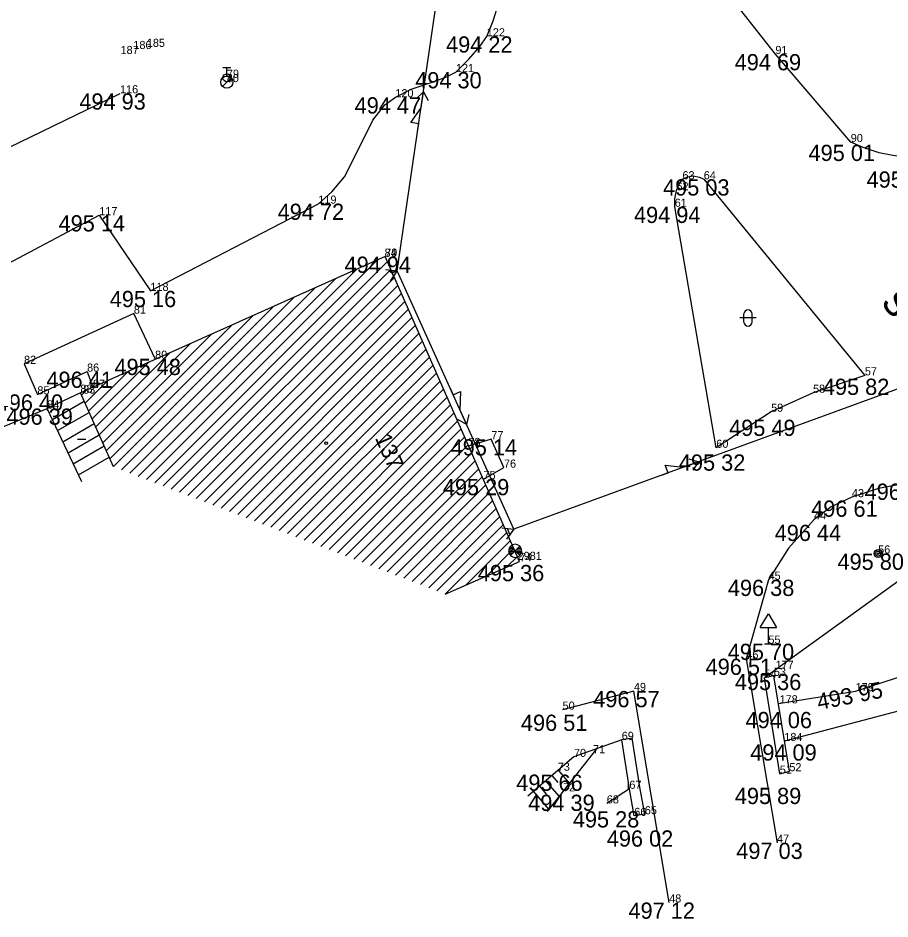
# Model space of a CAD drawing. Extents: x -559180 to -551373, y -1076947 to -1072071.
# Drawn here: x -553489.1 to -553435.4, y -1076713.8 to -1076658.3 of the extents above; entities that cross this region are included whole.
import ezdxf

# ---------------------------------------------------------------- set-up
doc = ezdxf.new("R2010")
doc.units = 0
for name, color, linetype in [('12_PLOTY', 7, 'Continuous'), ('14_BUDOVY', 7, 'Continuous'), ('17_KOMUNIKACE', 7, 'Continuous'), ('18_POLOHOPIS', 7, 'Continuous'), ('1_VODA_ZN', 7, 'Continuous'), ('20_EL_ZN', 7, 'Continuous'), ('23_HRANY', 7, 'Continuous'), ('26_SRAFY', 7, 'Continuous'), ('27_HRANA_PATA', 7, 'Continuous'), ('28_VODA', 7, 'Continuous'), ('32', 7, 'Continuous'), ('33', 7, 'Continuous'), ('3_BODY', 7, 'Continuous'), ('45_ZN_KULTURY', 7, 'Continuous'), ('47_ZN_STAV_OBJ$', 7, 'Continuous'), ('48_DOPRAVA_ZN', 7, 'Continuous'), ('52_POPIS_UCELOVY', 7, 'Continuous'), ('54_C_POPISNA', 7, 'Continuous'), ('6_VYSKY', 7, 'Continuous'), ('NNnadzemní', 7, 'Continuous')]:
    doc.layers.add(name, color=color, linetype=linetype)

# ---------------------------------------------------------------- blocks, each defined once
blk = doc.blocks.new('POINT_DISPLAY')
blk.add_line((0, 0), (0, 0))
blk = doc.blocks.new('DZ')
at = {"layer": '48_DOPRAVA_ZN'}
for p, q in [((-0.5, 1), (0, 1.85)), ((0, 1.85), (0.5, 1)), ((-0.5, 1), (0.5, 1)), ((0, 0), (0, 1)), ((-0.25, 0), (0.25, 0))]:
    blk.add_line(p, q, dxfattribs=at)
blk = doc.blocks.new('SLB')
at = {"layer": '20_EL_ZN'}
for radius in [0.25, 0.158, 0.05]:
    blk.add_circle((0, 0), radius, dxfattribs=at)
blk = doc.blocks.new('BZ')
at = {"layer": '47_ZN_STAV_OBJ$'}
blk.add_circle((0, 0), 0.0875, dxfattribs=at)
blk = doc.blocks.new('BD')
at = {"layer": '47_ZN_STAV_OBJ$'}
blk.add_line((-0.25, 0), (0.25, 0), dxfattribs=at)
blk = doc.blocks.new('NEPLOD')
at = {"layer": '45_ZN_KULTURY'}
for p, q in [((0.519, 0.01), (-0.481, 0.01)), ((-0.231, -0.24), (-0.231, 0.26)), ((0.269, -0.24), (0.269, 0.26))]:
    blk.add_line(p, q, dxfattribs=at)
for centre, start, end in [((0.019, 0.26), 0, 180), ((0.019, -0.24), 180, 0)]:
    blk.add_arc(centre, 0.25, start, end, dxfattribs=at)
blk = doc.blocks.new('SV')
at = {"layer": '1_VODA_ZN'}
blk.add_circle((0, 0), 0.25, dxfattribs=at)
blk = doc.blocks.new('HYP')
at = {"layer": '1_VODA_ZN'}
for p, q in [((-0.25, 0.9), (0.25, 0.9)), ((0, 0.375), (0, 0.9)), ((-0.265, -0.265), (0.265, 0.265))]:
    blk.add_line(p, q, dxfattribs=at)
blk.add_circle((0, 0), 0.375, dxfattribs=at)
blk = doc.blocks.new('NZ')
at = {"layer": '33'}
for p, q in [((-0.074, 0.04), (-0.401, 0.04)), ((-0.158, 0.151), (-0.349, 0.151)), ((0.376, 0.036), (0.055, 0.035)), ((0.348, 0.134), (0.145, 0.135)), ((-0.074, -0.054), (-0.372, -0.055)), ((-0.175, -0.16), (-0.361, -0.16)), ((0.37, -0.065), (0.089, -0.064)), ((0.342, -0.155), (0.162, -0.155))]:
    blk.add_line(p, q, dxfattribs=at)
for points in [[(0, 0), (-0.285, 0.285)], [(-0.285, -0.285), (0, 0)], [(0.285, 0.285), (0, 0)], [(0, 0), (0.285, -0.285)]]:
    blk.add_lwpolyline(points, dxfattribs=at)
for start, end in [(135.0044, 225.0044), (45, 135), (315.0044, 45.0044), (225, 315)]:
    blk.add_arc((0, 0), 0.403, start, end, dxfattribs=at)
blk = doc.blocks.new('KONZ')
at = {"layer": '20_EL_ZN'}
for p, q in [((-0.351, 0), (0, 0.65)), ((0, 0.65), (0.4, 0)), ((0.215, 0.3), (-0.188, 0.3))]:
    blk.add_line(p, q, dxfattribs=at)
blk = doc.blocks.new('ELNN')
at = {"layer": '20_EL_ZN'}
for p, q in [((0, 0), (0.5, 0)), ((0.5, 0), (0.5, 0.5)), ((0.5, 0.5), (1.5, 0)), ((1.5, 0), (2.5, 0))]:
    blk.add_line(p, q, dxfattribs=at)
blk.add_lwpolyline([(2, 0.375), (2.5, 0), (2, -0.375)], dxfattribs=at)

msp = doc.modelspace()

# ---------------------------------------------------------------- linework, layer by layer
at = {"layer": '12_PLOTY'}
msp.add_line((-553490.15, -1076683.51), (-553487.27, -1076682.33), dxfattribs=at)
at = {"layer": '14_BUDOVY'}
for p, q in [((-553466.45, -1076672.98), (-553485.22, -1076681.36)), ((-553458.18, -1076691.74), (-553466.45, -1076672.98)), ((-553485.22, -1076681.36), (-553487.27, -1076682.33)), ((-553483.182, -1076685.926), (-553485.22, -1076681.36)), ((-553485.131, -1076686.85), (-553487.27, -1076682.33)), ((-553462.755, -1076693.757), (-553458.18, -1076691.74))]:
    msp.add_line(p, q, dxfattribs=at)
at = {"layer": '17_KOMUNIKACE'}
for p, q in [((-553442.43, -1076660.51), (-553449.75, -1076651.19)), ((-553437.79, -1076665.93), (-553442.43, -1076660.51)), ((-553490.98, -1076666.9), (-553482.78, -1076662.93)), ((-553446.84, -1076668.22), (-553436.92, -1076680.29)), ((-553480.91, -1076675.09), (-553470.57, -1076669.72)), ((-553446.07, -1076684.75), (-553448.63, -1076669.91)), ((-553497.8, -1076677.69), (-553484.06, -1076670.43)), ((-553484.06, -1076670.43), (-553480.91, -1076675.09)), ((-553436.92, -1076680.29), (-553440.11, -1076681.36)), ((-553440.11, -1076681.36), (-553442.69, -1076682.53)), ((-553442.69, -1076682.53), (-553446.07, -1076684.75)), ((-553442.85, -1076692.87), (-553444.22, -1076697.73)), ((-553444.22, -1076697.73), (-553442.33, -1076709.06)), ((-553451.14, -1076699.72), (-553455.53, -1076700.87)), ((-553448.97, -1076712.74), (-553451.14, -1076699.72))]:
    msp.add_line(p, q, dxfattribs=at)
for points in [[(-553460.2, -1076659.42), (-553459.798, -1076658.474), (-553459.578, -1076657.747), (-553459.45, -1076656.63)], [(-553462.1, -1076661.62), (-553461.3, -1076660.823), (-553460.624, -1076660.045), (-553460.2, -1076659.42)], [(-553465.83, -1076663.17), (-553464.865, -1076662.681), (-553463.632, -1076662.259), (-553462.719, -1076661.938), (-553462.1, -1076661.62)], [(-553470.57, -1076669.72), (-553469.74, -1076668.986), (-553468.955, -1076668.073), (-553467.713, -1076665.59), (-553467.206, -1076664.576), (-553466.471, -1076663.638), (-553465.83, -1076663.17)], [(-553434.38, -1076666.87), (-553435.205, -1076666.747), (-553436.046, -1076666.591), (-553437.033, -1076666.272), (-553437.79, -1076665.93)], [(-553448.15, -1076668.22), (-553447.837, -1076668.059), (-553447.488, -1076668.014), (-553447.105, -1076668.081), (-553446.84, -1076668.22)], [(-553448.52, -1076668.9), (-553448.355, -1076668.52), (-553448.15, -1076668.22)], [(-553448.63, -1076669.91), (-553448.625, -1076669.421), (-553448.52, -1076668.9)], [(-553434.43, -1076686.95), (-553436.09, -1076687.26), (-553437.72, -1076687.79)], [(-553437.72, -1076687.79), (-553438.993, -1076688.374), (-553440.05, -1076689.16)], [(-553440.05, -1076689.16), (-553441.619, -1076690.919), (-553442.85, -1076692.87)]]:
    msp.add_lwpolyline(points, dxfattribs=at)
at = {"layer": '18_POLOHOPIS'}
for p, q in [((-553481.93, -1076676.49), (-553488.69, -1076679.58)), ((-553480.62, -1076679.27), (-553481.93, -1076676.49)), ((-553488.69, -1076679.58), (-553487.87, -1076681.46)), ((-553487.87, -1076681.46), (-553484.81, -1076680.06)), ((-553484.81, -1076680.06), (-553484.45, -1076681.06)), ((-553459.92, -1076684.22), (-553461.33, -1076684.64)), ((-553459.14, -1076685.97), (-553459.92, -1076684.22)), ((-553460.4, -1076686.67), (-553459.14, -1076685.97)), ((-553442.52, -1076698.79), (-553443.09, -1076698.9)), ((-553442.16, -1076704.81), (-553443.09, -1076698.9)), ((-553441.57, -1076704.66), (-553442.52, -1076698.79)), ((-553451.24, -1076702.63), (-553451.89, -1076702.73)), ((-553451.42, -1076705.74), (-553451.89, -1076702.73)), ((-553450.77, -1076705.64), (-553451.24, -1076702.63)), ((-553442.16, -1076704.81), (-553441.57, -1076704.66)), ((-553450.47, -1076707.31), (-553450.77, -1076705.64)), ((-553451.12, -1076707.41), (-553451.42, -1076705.74)), ((-553450.47, -1076707.31), (-553451.12, -1076707.41))]:
    msp.add_line(p, q, dxfattribs=at)
at = {"layer": '23_HRANY'}
for p, q in [((-553451.89, -1076702.73), (-553454.83, -1076703.78)), ((-553451.42, -1076705.74), (-553452.81, -1076706.64))]:
    msp.add_line(p, q, dxfattribs=at)
at = {"layer": '26_SRAFY'}
for p, q in [((-553455.114, -1076705.397), (-553455.793, -1076704.598)), ((-553455.802, -1076705.36), (-553456.174, -1076704.922)), ((-553456.498, -1076706.085), (-553456.936, -1076705.57)), ((-553455.745, -1076706.199), (-553456.555, -1076705.246)), ((-553456.376, -1076707), (-553457.317, -1076705.894))]:
    msp.add_line(p, q, dxfattribs=at)
at = {"layer": '27_HRANA_PATA'}
for p, q in [((-553430.39, -1076689.72), (-553443.09, -1076698.9)), ((-553454.83, -1076703.78), (-553457.672, -1076706.196))]:
    msp.add_line(p, q, dxfattribs=at)
at = {"layer": '28_VODA'}
for p, q in [((-553437.49, -1076699.73), (-553433.68, -1076698.48)), ((-553442.245, -1076700.492), (-553437.49, -1076699.73)), ((-553432.97, -1076700.47), (-553441.871, -1076702.798)), ((-553453.454, -1076703.289), (-553456.481, -1076707.134))]:
    msp.add_line(p, q, dxfattribs=at)
at = {"layer": '32'}
for p, q in [((-553480.645, -1076686.899), (-553466.95, -1076673.203)), ((-553480.134, -1076687.094), (-553466.318, -1076673.279)), ((-553481.156, -1076686.703), (-553468.227, -1076673.774)), ((-553479.623, -1076687.29), (-553466.102, -1076673.769)), ((-553481.668, -1076686.507), (-553469.505, -1076674.344)), ((-553479.112, -1076687.486), (-553465.886, -1076674.26)), ((-553482.179, -1076686.311), (-553470.782, -1076674.914)), ((-553478.601, -1076687.682), (-553465.669, -1076674.751)), ((-553482.69, -1076686.115), (-553472.06, -1076675.484)), ((-553478.089, -1076687.878), (-553465.453, -1076675.242)), ((-553477.578, -1076688.074), (-553465.237, -1076675.733)), ((-553483.19, -1076685.908), (-553473.337, -1076676.055)), ((-553477.067, -1076688.27), (-553465.02, -1076676.223)), ((-553483.408, -1076685.419), (-553474.614, -1076676.625)), ((-553476.556, -1076688.466), (-553464.804, -1076676.714)), ((-553483.627, -1076684.93), (-553475.892, -1076677.195)), ((-553476.045, -1076688.662), (-553464.588, -1076677.205)), ((-553483.845, -1076684.441), (-553477.169, -1076677.766)), ((-553475.534, -1076688.858), (-553464.371, -1076677.696)), ((-553484.063, -1076683.952), (-553478.447, -1076678.336)), ((-553475.023, -1076689.054), (-553464.155, -1076678.186)), ((-553484.281, -1076683.463), (-553479.724, -1076678.906)), ((-553474.511, -1076689.25), (-553463.939, -1076678.677)), ((-553484.499, -1076682.974), (-553481.002, -1076679.477)), ((-553474, -1076689.446), (-553463.722, -1076679.168)), ((-553473.489, -1076689.642), (-553463.506, -1076679.659)), ((-553484.718, -1076682.486), (-553482.279, -1076680.047)), ((-553472.978, -1076689.838), (-553463.29, -1076680.149)), ((-553484.936, -1076681.997), (-553483.556, -1076680.617)), ((-553472.467, -1076690.034), (-553463.073, -1076680.64)), ((-553485.154, -1076681.508), (-553484.834, -1076681.188)), ((-553471.956, -1076690.23), (-553462.857, -1076681.131)), ((-553486.948, -1076683.01), (-553484.988, -1076681.879)), ((-553471.445, -1076690.426), (-553462.64, -1076681.622)), ((-553470.933, -1076690.622), (-553462.424, -1076682.112)), ((-553486.626, -1076683.69), (-553484.681, -1076682.567)), ((-553470.422, -1076690.818), (-553462.208, -1076682.603)), ((-553486.304, -1076684.371), (-553484.374, -1076683.256)), ((-553469.911, -1076691.014), (-553461.991, -1076683.094)), ((-553485.982, -1076685.051), (-553484.066, -1076683.945)), ((-553469.4, -1076691.21), (-553461.775, -1076683.585)), ((-553468.889, -1076691.406), (-553461.559, -1076684.075)), ((-553485.661, -1076685.731), (-553483.759, -1076684.633)), ((-553468.378, -1076691.601), (-553461.342, -1076684.566)), ((-553467.866, -1076691.797), (-553461.126, -1076685.057)), ((-553485.339, -1076686.411), (-553483.452, -1076685.322)), ((-553467.355, -1076691.993), (-553460.91, -1076685.548)), ((-553466.844, -1076692.189), (-553460.693, -1076686.039)), ((-553466.333, -1076692.385), (-553460.477, -1076686.529)), ((-553465.822, -1076692.581), (-553460.261, -1076687.02)), ((-553465.311, -1076692.777), (-553460.044, -1076687.511)), ((-553464.8, -1076692.973), (-553459.828, -1076688.002)), ((-553464.288, -1076693.169), (-553459.612, -1076688.492)), ((-553463.777, -1076693.365), (-553459.395, -1076688.983)), ((-553463.266, -1076693.561), (-553459.179, -1076689.474)), ((-553462.755, -1076693.757), (-553458.963, -1076689.965)), ((-553461.49, -1076693.199), (-553458.746, -1076690.455)), ((-553460.226, -1076692.642), (-553458.53, -1076690.946)), ((-553458.961, -1076692.084), (-553458.314, -1076691.437)), ((-553451.481, -1076705.779), (-553451.481, -1076705.349))]:
    msp.add_line(p, q, dxfattribs=at)
at = {"layer": 'NNnadzemní'}
for p, q in [((-553465.711, -1076673.852), (-553463.01, -1076655.36)), ((-553458.537, -1076689.757), (-553465.711, -1076673.852)), ((-553419.66, -1076675.57), (-553458.537, -1076689.757))]:
    msp.add_line(p, q, dxfattribs=at)

# ---------------------------------------------------------------- block references
at = {"layer": '1_VODA_ZN'}
for name, p in [('POINT_DISPLAY', (-553460.2, -1076659.42)), ('POINT_DISPLAY', (-553481.96, -1076660.2)), ('POINT_DISPLAY', (-553481.13, -1076660.07)), ('POINT_DISPLAY', (-553482.75, -1076660.51)), ('POINT_DISPLAY', (-553442.43, -1076660.51)), ('HYP', (-553476.21, -1076662.24)), ('SV', (-553476.2, -1076661.97)), ('POINT_DISPLAY', (-553462.1, -1076661.62)), ('POINT_DISPLAY', (-553476.21, -1076662.24)), ('POINT_DISPLAY', (-553476.2, -1076661.97)), ('POINT_DISPLAY', (-553482.78, -1076662.93)), ('POINT_DISPLAY', (-553465.83, -1076663.17)), ('POINT_DISPLAY', (-553437.79, -1076665.93)), ('POINT_DISPLAY', (-553448.15, -1076668.22)), ('POINT_DISPLAY', (-553446.84, -1076668.22)), ('POINT_DISPLAY', (-553448.52, -1076668.9)), ('POINT_DISPLAY', (-553470.57, -1076669.72)), ('POINT_DISPLAY', (-553448.63, -1076669.91)), ('POINT_DISPLAY', (-553484.06, -1076670.43)), ('POINT_DISPLAY', (-553466.49, -1076672.99)), ('POINT_DISPLAY', (-553466.45, -1076672.98)), ('POINT_DISPLAY', (-553480.91, -1076675.09)), ('POINT_DISPLAY', (-553481.93, -1076676.49)), ('POINT_DISPLAY', (-553488.69, -1076679.58)), ('POINT_DISPLAY', (-553480.62, -1076679.27)), ('POINT_DISPLAY', (-553484.81, -1076680.06)), ('POINT_DISPLAY', (-553436.92, -1076680.29)), ('POINT_DISPLAY', (-553484.45, -1076681.06)), ('POINT_DISPLAY', (-553487.87, -1076681.46)), ('POINT_DISPLAY', (-553485.22, -1076681.36)), ('POINT_DISPLAY', (-553485.05, -1076681.41)), ('POINT_DISPLAY', (-553440.11, -1076681.36)), ('POINT_DISPLAY', (-553487.27, -1076682.33)), ('POINT_DISPLAY', (-553442.69, -1076682.53)), ('POINT_DISPLAY', (-553461.33, -1076684.64)), ('POINT_DISPLAY', (-553459.92, -1076684.22)), ('POINT_DISPLAY', (-553446.07, -1076684.75)), ('POINT_DISPLAY', (-553459.14, -1076685.97)), ('POINT_DISPLAY', (-553460.4, -1076686.67)), ('POINT_DISPLAY', (-553437.72, -1076687.79)), ('POINT_DISPLAY', (-553440.05, -1076689.16)), ('POINT_DISPLAY', (-553458.45, -1076691.09)), ('POINT_DISPLAY', (-553458.45, -1076691.092)), ('POINT_DISPLAY', (-553436.1, -1076691.26)), ('POINT_DISPLAY', (-553458.3, -1076691.65)), ('POINT_DISPLAY', (-553458.18, -1076691.74)), ('POINT_DISPLAY', (-553442.85, -1076692.87)), ('POINT_DISPLAY', (-553442.86, -1076696.81)), ('POINT_DISPLAY', (-553444.22, -1076697.73)), ('POINT_DISPLAY', (-553442.42, -1076698.36)), ('POINT_DISPLAY', (-553443.09, -1076698.9)), ('POINT_DISPLAY', (-553442.52, -1076698.79)), ('POINT_DISPLAY', (-553451.14, -1076699.72)), ('POINT_DISPLAY', (-553437.49, -1076699.73)), ('POINT_DISPLAY', (-553442.17, -1076700.48)), ('POINT_DISPLAY', (-553455.53, -1076700.87)), ('POINT_DISPLAY', (-553451.89, -1076702.73)), ('POINT_DISPLAY', (-553441.88, -1076702.8)), ('POINT_DISPLAY', (-553454.83, -1076703.78)), ('POINT_DISPLAY', (-553453.66, -1076703.55)), ('POINT_DISPLAY', (-553455.83, -1076704.63)), ('POINT_DISPLAY', (-553442.16, -1076704.81)), ('POINT_DISPLAY', (-553441.57, -1076704.66)), ('POINT_DISPLAY', (-553455.51, -1076705.9)), ('POINT_DISPLAY', (-553451.42, -1076705.74)), ('POINT_DISPLAY', (-553452.81, -1076706.64)), ('POINT_DISPLAY', (-553450.47, -1076707.31)), ('POINT_DISPLAY', (-553451.12, -1076707.41)), ('POINT_DISPLAY', (-553442.33, -1076709.06)), ('POINT_DISPLAY', (-553448.97, -1076712.74))]:
    msp.add_blockref(name, p, dxfattribs=at)
at = {"layer": '20_EL_ZN'}
for name, p, xscale, yscale, rotation in [('ELNN', (-553464.462, -1076665.299), 0.9999985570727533, 0.9999985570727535, 81.69006692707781), ('KONZ', (-553466.311, -1076674.102), 0.9999984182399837, 0.9999984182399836, -67.4172004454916), ('ELNN', (-553462.471, -1076681.036), 0.9999988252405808, 0.9999988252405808, -65.72218245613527), ('ELNN', (-553449.51, -1076686.463), 0.9999974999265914, 0.9999974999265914, 20.048003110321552), ('KONZ', (-553459.137, -1076690.007), 0.9999984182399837, 0.9999984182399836, -67.4172004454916)]:
    msp.add_blockref(name, p, dxfattribs=dict(at, xscale=xscale, yscale=yscale, rotation=rotation))
msp.add_blockref('SLB', (-553436.1, -1076691.26), dxfattribs=at)
at = {"layer": '32'}
for p in [(-553487.27, -1076682.33), (-553462.755, -1076693.757)]:
    msp.add_blockref('POINT_DISPLAY', p, dxfattribs=at)
at = {"layer": '33'}
msp.add_blockref('NZ', (-553458.45, -1076691.09), dxfattribs=at)
at = {"layer": '45_ZN_KULTURY'}
msp.add_blockref('NEPLOD', (-553444.132, -1076676.767), dxfattribs=at)
at = {"layer": '47_ZN_STAV_OBJ$'}
for name, p in [('BD', (-553485.144, -1076684.211)), ('BZ', (-553470.093, -1076684.461))]:
    msp.add_blockref(name, p, dxfattribs=at)
at = {"layer": '48_DOPRAVA_ZN'}
msp.add_blockref('DZ', (-553442.86, -1076696.81), dxfattribs=at)

# ---------------------------------------------------------------- texts
at = {"layer": '3_BODY'}
for s, p in [('122', (-553460.2, -1076659.42)), ('186', (-553481.96, -1076660.2)), ('185', (-553481.13, -1076660.07)), ('187', (-553482.75, -1076660.51)), ('91', (-553442.43, -1076660.51)), ('121', (-553462.1, -1076661.62)), ('80', (-553476.21, -1076662.24)), ('79', (-553476.2, -1076661.97)), ('116', (-553482.78, -1076662.93)), ('120', (-553465.83, -1076663.17)), ('90', (-553437.79, -1076665.93)), ('63', (-553448.15, -1076668.22)), ('64', (-553446.84, -1076668.22)), ('62', (-553448.52, -1076668.9)), ('119', (-553470.57, -1076669.72)), ('61', (-553448.63, -1076669.91)), ('117', (-553484.06, -1076670.43)), ('84', (-553466.49, -1076672.99)), ('79', (-553466.45, -1076672.98)), ('118', (-553480.91, -1076675.09)), ('81', (-553481.93, -1076676.49)), ('82', (-553488.69, -1076679.58)), ('80', (-553480.62, -1076679.27)), ('86', (-553484.81, -1076680.06)), ('57', (-553436.92, -1076680.29)), ('87', (-553484.45, -1076681.06)), ('85', (-553487.87, -1076681.46)), ('83', (-553485.22, -1076681.36)), ('83', (-553485.05, -1076681.41)), ('58', (-553440.11, -1076681.36)), ('84', (-553487.27, -1076682.33)), ('59', (-553442.69, -1076682.53)), ('77', (-553459.92, -1076684.22)), ('78', (-553461.33, -1076684.64)), ('60', (-553446.07, -1076684.75)), ('76', (-553459.14, -1076685.97)), ('75', (-553460.4, -1076686.67)), ('43', (-553437.72, -1076687.79)), ('44', (-553440.05, -1076689.16)), ('56', (-553436.1, -1076691.26)), ('2981', (-553458.3, -1076691.65)), ('74', (-553458.18, -1076691.74)), ('45', (-553442.85, -1076692.87)), ('55', (-553442.86, -1076696.81)), ('46', (-553444.22, -1076697.73)), ('177', (-553442.42, -1076698.36)), ('54', (-553443.09, -1076698.9)), ('53', (-553442.52, -1076698.79)), ('49', (-553451.14, -1076699.72)), ('179', (-553437.49, -1076699.73)), ('178', (-553442.17, -1076700.48)), ('50', (-553455.53, -1076700.87)), ('69', (-553451.89, -1076702.73)), ('184', (-553441.88, -1076702.8)), ('70', (-553454.83, -1076703.78)), ('71', (-553453.66, -1076703.55)), ('73', (-553455.83, -1076704.63)), ('51', (-553442.16, -1076704.81)), ('52', (-553441.57, -1076704.66)), ('72', (-553455.51, -1076705.9)), ('67', (-553451.42, -1076705.74)), ('68', (-553452.81, -1076706.64)), ('65', (-553450.47, -1076707.31)), ('66', (-553451.12, -1076707.41)), ('47', (-553442.33, -1076709.06)), ('48', (-553448.97, -1076712.74))]:
    msp.add_text(s, height=0.5, dxfattribs=at).set_placement(p)
at = {"layer": '52_POPIS_UCELOVY'}
msp.add_text('státní silnice č. 11', height=2, rotation=309.4158, dxfattribs=at).set_placement((-553435.965, -1076675.842))
at = {"layer": '54_C_POPISNA'}
msp.add_text('137', height=1, rotation=293.7894, dxfattribs=at).set_placement((-553467.098, -1076684.137))
at = {"layer": '6_VYSKY'}
for s, p in [('494 22', (-553462.705, -1076660.42)), ('494 69', (-553444.935, -1076661.51)), ('494 30', (-553464.605, -1076662.62)), ('494 93', (-553485.285, -1076663.93)), ('494 47', (-553468.335, -1076664.17)), ('495 01', (-553440.388, -1076667.093)), ('495 22', (-553436.814, -1076668.736)), ('495 03', (-553449.345, -1076669.22)), ('494 72', (-553473.075, -1076670.72)), ('494 94', (-553451.135, -1076670.91)), ('495 14', (-553486.565, -1076671.43)), ('494 94', (-553468.955, -1076673.98)), ('495 16', (-553483.415, -1076676.09)), ('495 48', (-553483.125, -1076680.27)), ('496 41', (-553487.315, -1076681.06)), ('495 82', (-553439.506, -1076681.494)), ('496 40', (-553490.375, -1076682.46)), ('496 39', (-553489.775, -1076683.33)), ('495 49', (-553445.277, -1076684.019)), ('495 14', (-553462.425, -1076685.22)), ('495 32', (-553448.371, -1076686.157)), ('495 29', (-553462.905, -1076687.67)), ('496 92', (-553436.935, -1076687.95)), ('496 61', (-553440.225, -1076688.994)), ('496 44', (-553442.473, -1076690.486)), ('495 80', (-553438.605, -1076692.26)), ('495 36', (-553460.752, -1076692.959)), ('496 38', (-553445.355, -1076693.87)), ('495 70', (-553445.365, -1076697.81)), ('496 51', (-553446.725, -1076698.73)), ('495 36', (-553444.925, -1076699.664)), ('496 57', (-553453.645, -1076700.72)), ('496 51', (-553458.097, -1076702.176)), ('494 06', (-553444.267, -1076702.01)), ('494 09', (-553443.977, -1076704.004)), ('495 66', (-553458.385, -1076705.866)), ('495 89', (-553444.927, -1076706.679)), ('494 39', (-553457.648, -1076707.104)), ('495 28', (-553454.901, -1076708.121)), ('496 02', (-553452.81, -1076709.3)), ('497 03', (-553444.835, -1076710.06)), ('497 12', (-553451.475, -1076713.74))]:
    msp.add_text(s, height=1, dxfattribs=at).set_placement(p)
msp.add_text('493 95', height=1, rotation=10.968, dxfattribs=at).set_placement((-553439.763, -1076700.891))

doc.saveas('drawing.dxf')
